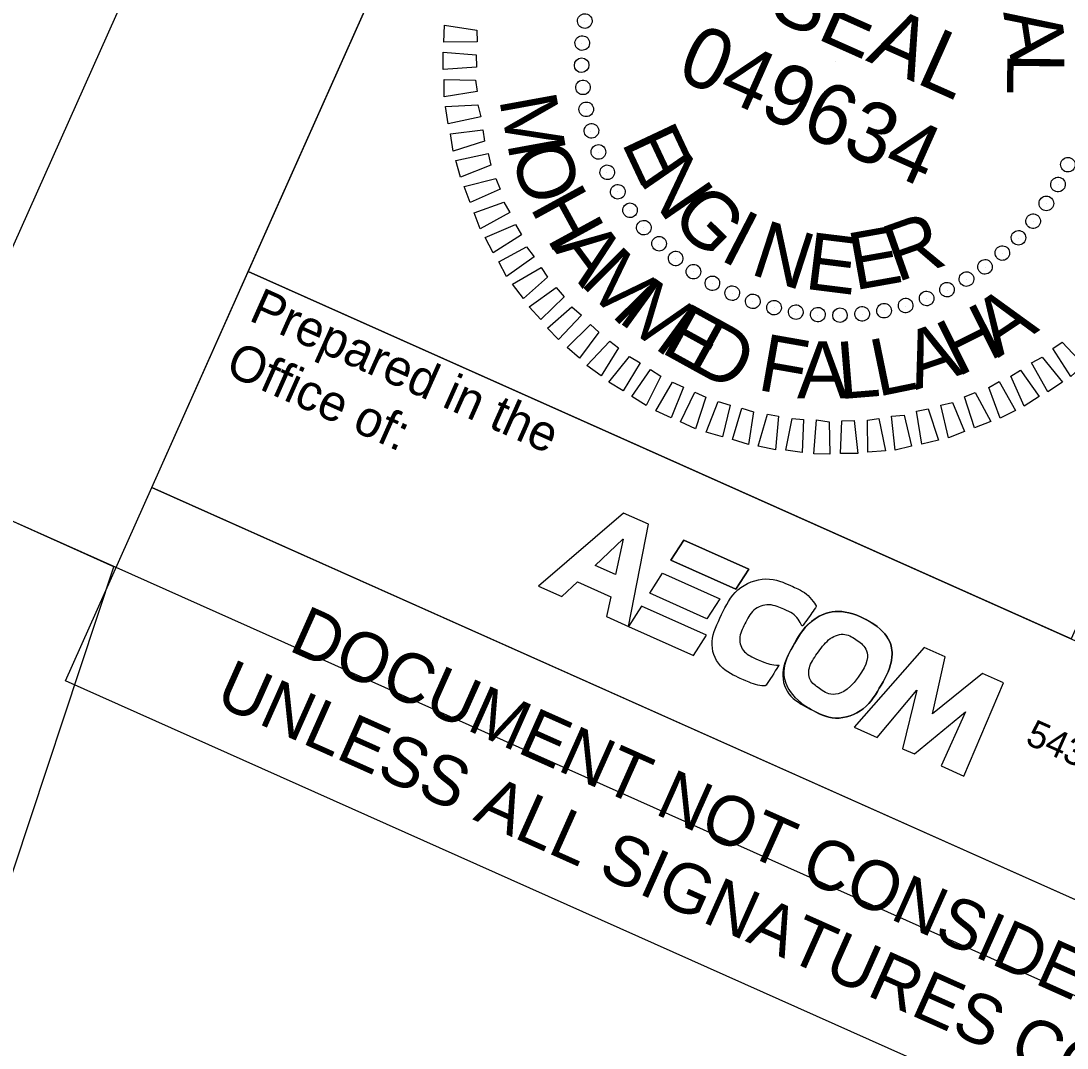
# Model space of a CAD drawing. Extents: x 2297991 to 2299183, y 599186 to 600200.
# Drawn here: x 2299005.9 to 2299075.6, y 599694 to 599762.5 of the extents above; entities that cross this region are included whole.
import ezdxf

# ---------------------------------------------------------------- set-up
doc = ezdxf.new("R2010")
doc.units = 0
for name, color, linetype in [('Default', 7, 'Continuous'), ('Exist DTM Drainline Cogo Comment', 7, 'Continuous'), ('Exist DTM Drainline Cogo Point CELL', 7, 'Continuous'), ('Exist Property Iron Pin Cogo Number', 7, 'Continuous'), ('Exist Roads Curbs Cogo Elevation', 7, 'Continuous'), ('Exist Roads Curbs Cogo Number', 7, 'Continuous'), ('Exist Roads EOP Cogo Comment', 7, 'Continuous'), ('Exist Roads EOP Cogo Elevation', 7, 'Continuous'), ('Exist Roads EOP Other Cogo Point CELL', 7, 'Continuous')]:
    doc.layers.add(name, color=color, linetype=linetype)

# ---------------------------------------------------------------- blocks, each defined once
blk = doc.blocks.new('block 3')
at = {"layer": 'Default'}
blk.add_open_spline([(0.12275, 0.09393), (0.12554, 0.09373), (0.12726, 0.09146), (0.12695, 0.08843), (0.12663, 0.08531), (0.12411, 0.08298), (0.12127, 0.08318), (0.11848, 0.08338), (0.11676, 0.08565), (0.11707, 0.08868), (0.11739, 0.0918), (0.11991, 0.09413), (0.12275, 0.09393)], degree=3, dxfattribs=at)
blk = doc.blocks.new('block 2')
at = {"layer": 'Default'}
for p, q in [((0.10234, 0.09375), (0.10197, 0.09133)), ((0.10966, 0.09375), (0.10234, 0.09375)), ((0.10929, 0.09133), (0.10966, 0.09375)), ((0.10197, 0.09133), (0.10929, 0.09133)), ((0.10137, 0.08733), (0.10174, 0.08975)), ((0.10174, 0.08975), (0.10818, 0.08975)), ((0.10818, 0.08975), (0.10782, 0.08733)), ((0.10782, 0.08733), (0.10137, 0.08733)), ((0.10114, 0.08576), (0.10078, 0.08333)), ((0.10846, 0.08576), (0.10114, 0.08576)), ((0.1081, 0.08333), (0.10846, 0.08576)), ((0.10078, 0.08333), (0.1081, 0.08333))]:
    blk.add_line(p, q, dxfattribs=at)
for points in [[(0.10929, 0.09133), (0.10197, 0.09133), (0.10234, 0.09375), (0.10966, 0.09375), (0.10929, 0.09133)], [(0.10782, 0.08733), (0.10137, 0.08733), (0.10174, 0.08975), (0.10818, 0.08975), (0.10782, 0.08733)], [(0.10846, 0.08576), (0.10114, 0.08576), (0.10078, 0.08333), (0.1081, 0.08333), (0.10846, 0.08576)]]:
    blk.add_lwpolyline(points, dxfattribs=at)
blk = doc.blocks.new('POINT_DISPLAY')
at = {"layer": 'Default'}
blk.add_line((0, 0), (0, 0), dxfattribs=at)

msp = doc.modelspace()

# ---------------------------------------------------------------- linework, layer by layer
at = {"layer": 'Exist DTM Drainline Cogo Comment'}
msp.add_lwpolyline([(2298345.556, 600145.915), (2298088.777, 599570.636), (2298910.614, 599203.781), (2299118.519, 599669.587), (2299008.922, 599718.518), (2299057.787, 599827.986)], close=True, dxfattribs=at)
at = {"layer": 'Exist DTM Drainline Cogo Point CELL'}
msp.add_lwpolyline([(2299048.604, 599807.413), (2299103.421, 599782.943), (2299075.906, 599721.305), (2299021.089, 599745.774)], close=True, dxfattribs=at)
at = {"layer": 'Exist Property Iron Pin Cogo Number'}
msp.add_lwpolyline([(2298166.712, 599708.439), (2298114.072, 599590.506), (2298857.043, 599258.855), (2299012.143, 599726.114), (2298998.588, 599732.165), (2299037.976, 599820.403), (2298552.347, 600037.18)], close=True, dxfattribs=at)
at = {"layer": 'Exist Roads Curbs Cogo Elevation'}
msp.add_lwpolyline([(2299021.089, 599745.774), (2299130.668, 599696.86), (2299124.249, 599682.479), (2299014.67, 599731.393)], close=True, dxfattribs=at)
at = {"layer": 'Exist Roads Curbs Cogo Number'}
for p, q in [((2299008.922, 599718.518), (2299014.67, 599731.393)), ((2299014.67, 599731.393), (2299124.269, 599682.47)), ((2299118.522, 599669.594), (2299008.922, 599718.518))]:
    msp.add_line(p, q, dxfattribs=at)
at = {"layer": 'Exist Roads EOP Cogo Comment'}
msp.add_lwpolyline([(2298353.139, 600126.103), (2298108.588, 599578.22), (2298903.031, 599223.593), (2299108.187, 599683.241), (2298998.588, 599732.165), (2299037.976, 599820.403)], close=True, dxfattribs=at)
at = {"layer": 'Exist Roads EOP Cogo Elevation'}
for p, q in [((2299046.079, 599729.684), (2299040.427, 599724.815)), ((2299047.749, 599728.939), (2299046.079, 599729.684)), ((2299046.421, 599722.14), (2299047.749, 599728.939)), ((2299044.192, 599726.204), (2299046.041, 599727.943)), ((2299046.055, 599727.937), (2299045.554, 599725.596)), ((2299046.041, 599727.943), (2299046.055, 599727.937)), ((2299045.554, 599725.596), (2299044.192, 599726.204)), ((2299040.427, 599724.815), (2299041.978, 599724.123)), ((2299041.978, 599724.123), (2299043.017, 599725.1)), ((2299043.017, 599725.1), (2299045.236, 599724.109)), ((2299045.236, 599724.109), (2299044.955, 599722.794)), ((2299044.955, 599722.794), (2299046.421, 599722.14)), ((2299066.119, 599720.739), (2299061.453, 599715.43)), ((2299067.508, 599720.119), (2299066.119, 599720.739)), ((2299066.674, 599716.322), (2299067.508, 599720.119)), ((2299070.005, 599719.005), (2299066.674, 599716.322)), ((2299071.395, 599718.384), (2299070.005, 599719.005)), ((2299062.985, 599714.746), (2299065.638, 599717.89)), ((2299065.638, 599717.89), (2299064.682, 599713.988)), ((2299068.756, 599712.17), (2299071.395, 599718.384)), ((2299065.462, 599713.64), (2299068.879, 599716.441)), ((2299068.879, 599716.441), (2299067.247, 599712.843)), ((2299061.453, 599715.43), (2299062.985, 599714.746)), ((2299064.682, 599713.988), (2299065.462, 599713.64)), ((2299067.247, 599712.843), (2299068.756, 599712.17))]:
    msp.add_line(p, q, dxfattribs=at)
for points in [[(2299044.955, 599722.794), (2299046.421, 599722.14), (2299047.749, 599728.939), (2299046.079, 599729.684), (2299040.427, 599724.815), (2299041.978, 599724.123), (2299043.017, 599725.1), (2299045.236, 599724.109), (2299044.955, 599722.794)], [(2299068.756, 599712.17), (2299071.395, 599718.384), (2299070.005, 599719.005), (2299066.674, 599716.322), (2299067.508, 599720.119), (2299066.119, 599720.739), (2299061.453, 599715.43), (2299062.985, 599714.746), (2299065.638, 599717.89), (2299064.682, 599713.988), (2299065.462, 599713.64), (2299068.879, 599716.441), (2299067.247, 599712.843), (2299068.756, 599712.17)]]:
    msp.add_lwpolyline(points, dxfattribs=at)
for points in [[(2299056.448, 599719.559), (2299055.949, 599719.553), (2299055.319, 599719.797), (2299055.016, 599719.932), (2299054.041, 599720.367), (2299053.692, 599721.321), (2299054.166, 599722.295), (2299054.667, 599723.324), (2299055.791, 599723.72), (2299056.863, 599723.242), (2299057.37, 599723.015), (2299057.741, 599722.649), (2299057.99, 599722.132), (2299057.99, 599722.132), (2299058.946, 599723.476), (2299058.946, 599723.476), (2299058.494, 599724.109), (2299058.046, 599724.486), (2299057.405, 599724.773), (2299055.63, 599725.565), (2299053.506, 599724.74), (2299052.615, 599722.91), (2299051.75, 599721.135), (2299052.356, 599719.346), (2299054.096, 599718.569), (2299054.399, 599718.434), (2299055.067, 599718.174), (2299055.565, 599718.18), (2299055.565, 599718.18), (2299056.448, 599719.559), (2299056.448, 599719.559)], [(2299056.448, 599719.559), (2299055.949, 599719.553), (2299055.319, 599719.797), (2299055.016, 599719.932), (2299054.041, 599720.367), (2299053.692, 599721.321), (2299054.166, 599722.295), (2299054.667, 599723.324), (2299055.791, 599723.72), (2299056.863, 599723.242), (2299057.37, 599723.015), (2299057.741, 599722.649), (2299057.99, 599722.132), (2299057.99, 599722.132), (2299058.946, 599723.476), (2299058.946, 599723.476), (2299058.494, 599724.109), (2299058.046, 599724.486), (2299057.405, 599724.773), (2299055.63, 599725.565), (2299053.506, 599724.74), (2299052.615, 599722.91), (2299051.75, 599721.135), (2299052.356, 599719.346), (2299054.096, 599718.569), (2299054.399, 599718.434), (2299055.067, 599718.174), (2299055.565, 599718.18), (2299055.565, 599718.18), (2299056.448, 599719.559), (2299056.448, 599719.559)], [(2299057.918, 599717.039), (2299056.822, 599717.982), (2299056.625, 599719.523), (2299057.475, 599721), (2299058.49, 599722.764), (2299060.596, 599723.474), (2299062.225, 599722.603)], [(2299062.225, 599722.603), (2299063.821, 599721.75), (2299064.242, 599719.953), (2299063.258, 599718.241), (2299062.242, 599716.478), (2299060.136, 599715.767), (2299058.507, 599716.638), (2299058.288, 599716.755), (2299058.092, 599716.89), (2299057.918, 599717.039)], [(2299061.724, 599718.746), (2299062.413, 599719.688), (2299062.388, 599720.673), (2299061.672, 599721.186), (2299060.885, 599721.75), (2299059.802, 599721.438), (2299059.073, 599720.443), (2299058.383, 599719.501), (2299058.409, 599718.516), (2299059.125, 599718.003), (2299059.912, 599717.44), (2299060.995, 599717.751), (2299061.724, 599718.746)], [(2299061.724, 599718.746), (2299062.413, 599719.688), (2299062.388, 599720.673), (2299061.672, 599721.186), (2299060.885, 599721.75), (2299059.802, 599721.438), (2299059.073, 599720.443), (2299058.383, 599719.501), (2299058.409, 599718.516), (2299059.125, 599718.003), (2299059.912, 599717.44), (2299060.995, 599717.751), (2299061.724, 599718.746)]]:
    msp.add_open_spline(points, degree=3, dxfattribs=at)
at = {"layer": 'Exist Roads EOP Other Cogo Point CELL'}
for points in [[(2299036.329, 599761.066), (2299034.108, 599761.059), (2299034.165, 599762.18), (2299036.31, 599761.85)], [(2299036.283, 599759.387), (2299034.067, 599759.229), (2299034.063, 599760.378), (2299036.277, 599760.201)], [(2299036.337, 599757.772), (2299034.147, 599757.419), (2299034.141, 599758.567), (2299036.229, 599758.523)], [(2299036.578, 599756.075), (2299034.409, 599755.602), (2299034.221, 599756.757), (2299036.378, 599756.867)], [(2299036.815, 599754.454), (2299034.744, 599753.789), (2299034.557, 599754.944), (2299036.706, 599755.204)], [(2299037.249, 599752.856), (2299035.229, 599752.056), (2299034.908, 599753.161), (2299037.078, 599753.633)], [(2299037.862, 599751.25), (2299035.877, 599750.362), (2299035.467, 599751.433), (2299037.59, 599751.964)], [(2299038.504, 599749.708), (2299036.542, 599748.624), (2299036.133, 599749.694), (2299038.112, 599750.4)], [(2299039.28, 599748.215), (2299037.414, 599747.014), (2299036.871, 599748.034), (2299038.887, 599748.909)], [(2299040.145, 599746.758), (2299038.299, 599745.436), (2299037.772, 599746.411), (2299039.632, 599747.429)], [(2299041.02, 599745.405), (2299039.421, 599743.975), (2299038.7, 599744.925), (2299040.6, 599746.036)], [(2299042.135, 599744.094), (2299040.57, 599742.574), (2299039.807, 599743.433), (2299041.595, 599744.705)], [(2299043.292, 599742.876), (2299041.747, 599741.237), (2299041.018, 599742.005), (2299042.649, 599743.422)], [(2299044.445, 599741.732), (2299043.161, 599740.013), (2299042.329, 599740.718), (2299043.894, 599742.237)], [(2299045.759, 599740.702), (2299044.588, 599738.822), (2299043.636, 599739.506), (2299045.181, 599741.145)], [(2299075.315, 599741.076), (2299076.741, 599739.551), (2299075.884, 599738.788), (2299074.684, 599740.655)], [(2299047.194, 599739.692), (2299046.068, 599737.829), (2299045.104, 599738.406), (2299046.495, 599740.114)], [(2299073.984, 599740.081), (2299075.342, 599738.402), (2299074.357, 599737.77), (2299073.26, 599739.701)], [(2299048.577, 599738.815), (2299047.59, 599736.853), (2299046.642, 599737.461), (2299047.879, 599739.239)], [(2299072.525, 599739.215), (2299073.767, 599737.442), (2299072.783, 599736.81), (2299071.894, 599738.796)], [(2299050.091, 599738.066), (2299049.259, 599736.035), (2299048.242, 599736.489), (2299049.351, 599738.397)], [(2299071.109, 599738.443), (2299072.206, 599736.512), (2299071.17, 599736.013), (2299070.416, 599738.051)], [(2299051.571, 599737.406), (2299050.892, 599735.306), (2299049.875, 599735.76), (2299050.832, 599737.736)], [(2299069.524, 599737.709), (2299070.546, 599735.775), (2299069.476, 599735.365), (2299068.811, 599737.436)], [(2299053.181, 599736.872), (2299052.684, 599734.764), (2299051.598, 599735.064), (2299052.4, 599737.109)], [(2299054.756, 599736.427), (2299054.413, 599734.251), (2299053.342, 599734.582), (2299053.976, 599736.664)], [(2299066.383, 599736.635), (2299067.079, 599734.55), (2299065.957, 599734.273), (2299065.605, 599736.464)], [(2299068.012, 599737.053), (2299068.807, 599735.109), (2299067.737, 599734.699), (2299067.233, 599736.884)], [(2299056.402, 599736.136), (2299056.212, 599733.892), (2299055.068, 599734.143), (2299055.685, 599736.271)], [(2299058.074, 599735.908), (2299057.988, 599733.728), (2299056.908, 599733.877), (2299057.329, 599735.981)], [(2299063.102, 599735.992), (2299063.544, 599733.836), (2299062.355, 599733.738), (2299062.351, 599735.883)], [(2299064.785, 599736.201), (2299065.268, 599734.137), (2299064.192, 599733.878), (2299063.942, 599736.135)], [(2299059.787, 599735.772), (2299059.821, 599733.611), (2299058.762, 599733.641), (2299058.951, 599735.886)], [(2299061.446, 599735.843), (2299061.693, 599733.663), (2299060.544, 599733.658), (2299060.63, 599735.838)]]:
    msp.add_lwpolyline(points, close=True, dxfattribs=at)
for centre, major_axis in [((2299043.508, 599762.458), (-0.48, 0.077)), ((2299043.339, 599760.991), (-0.485, 0.034)), ((2299043.299, 599759.514), (-0.486, -0.008)), ((2299043.388, 599758.04), (-0.483, -0.05)), ((2299043.605, 599756.579), (-0.477, -0.092)), ((2299043.948, 599755.142), (-0.467, -0.134)), ((2299044.416, 599753.741), (-0.454, -0.174)), ((2299075.691, 599752.892), (0.444, -0.198)), ((2299045.003, 599752.386), (-0.437, -0.213)), ((2299075.031, 599751.571), (0.425, -0.236)), ((2299045.707, 599751.087), (-0.417, -0.25)), ((2299074.258, 599750.312), (0.403, -0.272)), ((2299046.521, 599749.854), (-0.394, -0.285)), ((2299047.44, 599748.697), (-0.367, -0.319)), ((2299073.378, 599749.125), (0.377, -0.306)), ((2299072.398, 599748.02), (0.349, -0.338)), ((2299048.455, 599747.625), (-0.338, -0.349)), ((2299049.561, 599746.645), (-0.306, -0.377)), ((2299071.325, 599747.004), (0.319, -0.367)), ((2299070.169, 599746.086), (0.285, -0.394)), ((2299050.747, 599745.765), (-0.272, -0.403)), ((2299068.936, 599745.272), (0.25, -0.417)), ((2299052.006, 599744.992), (-0.236, -0.425)), ((2299067.637, 599744.568), (0.213, -0.437)), ((2299053.327, 599744.332), (-0.198, -0.444)), ((2299054.701, 599743.789), (-0.159, -0.459)), ((2299066.282, 599743.98), (0.174, -0.454)), ((2299056.117, 599743.368), (-0.118, -0.472)), ((2299063.444, 599743.169), (0.092, -0.477)), ((2299064.881, 599743.513), (0.134, -0.467)), ((2299057.564, 599743.072), (-0.077, -0.48)), ((2299059.032, 599742.904), (-0.034, -0.485)), ((2299060.508, 599742.864), (0.008, -0.486)), ((2299061.983, 599742.952), (0.05, -0.483))]:
    msp.add_ellipse(centre, major_axis=major_axis, ratio=0.999708, dxfattribs=at)

# ---------------------------------------------------------------- block references
at = {"layer": 'Exist Roads EOP Cogo Elevation', "xscale": 648.0018668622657, "yscale": 648.0018668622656, "rotation": -24.055238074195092}
for name in ['block 2', 'block 3']:
    msp.add_blockref(name, (2298964.779, 599699.448), dxfattribs=at)
at = {"layer": 'Exist Roads EOP Other Cogo Point CELL', "xscale": 41.41195952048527, "yscale": 41.41195952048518, "rotation": -24.05480821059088}
for p in [(2299043.492, 599762.453), (2299043.314, 599760.979), (2299060.231, 599759.787), (2299043.598, 599756.564), (2299043.918, 599755.127), (2299044.403, 599753.729), (2299044.977, 599752.364), (2299075.038, 599751.55), (2299045.698, 599751.08), (2299074.26, 599750.308), (2299046.507, 599749.832), (2299047.435, 599748.679), (2299073.392, 599749.106), (2299072.414, 599747.99), (2299048.434, 599747.604), (2299049.55, 599746.626), (2299071.339, 599746.991), (2299050.751, 599745.756), (2299070.186, 599746.064), (2299068.936, 599745.253), (2299051.994, 599744.98), (2299053.323, 599744.313), (2299067.653, 599744.532), (2299054.706, 599743.769), (2299066.289, 599743.959), (2299056.115, 599743.362), (2299057.564, 599743.048), (2299061.982, 599742.925), (2299063.453, 599743.155), (2299064.889, 599743.475), (2299059.038, 599742.87), (2299060.505, 599742.845)]:
    msp.add_blockref('POINT_DISPLAY', p, dxfattribs=at)

# ---------------------------------------------------------------- texts
at = {"layer": 'Exist Roads Curbs Cogo Number'}
for s, p in [('DOCUMENT NOT CONSIDERED FINAL', (2299023.684, 599720.572)), ('UNLESS ALL SIGNATURES COMPLETED', (2299018.754, 599716.99))]:
    msp.add_text(s, height=3.30002, rotation=335.94476, dxfattribs=at).set_placement(p)
at = {"layer": 'Exist Roads EOP Cogo Elevation'}
for s, height, p in [('Prepared in the ', 2.40001, (2299021.046, 599742.553)), ('Office of:', 2.4, (2299019.456, 599738.992)), ('5438 Wade Park Boulevard, Suite 200', 1.80001, (2299072.776, 599714.346))]:
    msp.add_text(s, height=height, rotation=335.94476, dxfattribs=at).set_placement(p)
at = {"layer": 'Exist Roads EOP Other Cogo Point CELL'}
for s, height, rotation, p in [('SEAL', 4.0496, 335.94519, (2299055.564, 599762.795)), ('A', 3.807, 278.70546, (2299071.377, 599763.047)), ('049634', 4.0508, 335.94519, (2299049.473, 599758.71)), ('L', 3.807, 269.34604, (2299071.659, 599760.37)), ('M', 3.807, 280.35589, (2299037.79, 599757.272)), ('E', 3.807, 295.22208, (2299045.913, 599754.387)), ('O', 3.807, 289.45197, (2299038.483, 599753.642)), ('N', 3.807, 304.57915, (2299047.038, 599751.921)), ('H', 3.807, 298.61032, (2299039.813, 599750.064)), ('G', 3.807, 315.4484, (2299049.093, 599749.241)), ('I', 3.807, 332.64639, (2299052.395, 599746.611)), ('R', 3.807, 19.4266, (2299064.298, 599745.038)), ('N', 3.807, 342.00158, (2299054.432, 599745.628)), ('E', 3.807, 10.06928, (2299061.47, 599744.517)), ('A', 3.807, 306.49434, (2299041.345, 599747.329)), ('E', 3.807, 352.91206, (2299058.08, 599744.636)), ('M', 3.807, 314.87061, (2299043.11, 599744.986)), ('M', 3.807, 323.96159, (2299045.635, 599742.484)), ('A', 3.807, 33.82348, (2299071.051, 599740.001)), ('E', 3.807, 331.08825, (2299048.471, 599740.442)), ('H', 3.807, 26.62829, (2299068.34, 599738.727)), ('D', 3.807, 331.08825, (2299050.221, 599739.481)), ('F', 3.807, 350.02796, (2299054.918, 599737.905)), ('A', 3.807, 18.82402, (2299065.56, 599737.873)), ('A', 3.807, 359.92861, (2299057.637, 599737.323)), ('L', 3.807, 4.6735, (2299060.46, 599737.265)), ('L', 3.807, 11.63875, (2299063.006, 599737.424))]:
    msp.add_text(s, height=height, rotation=rotation, dxfattribs=at).set_placement(p)

doc.saveas('drawing.dxf')
